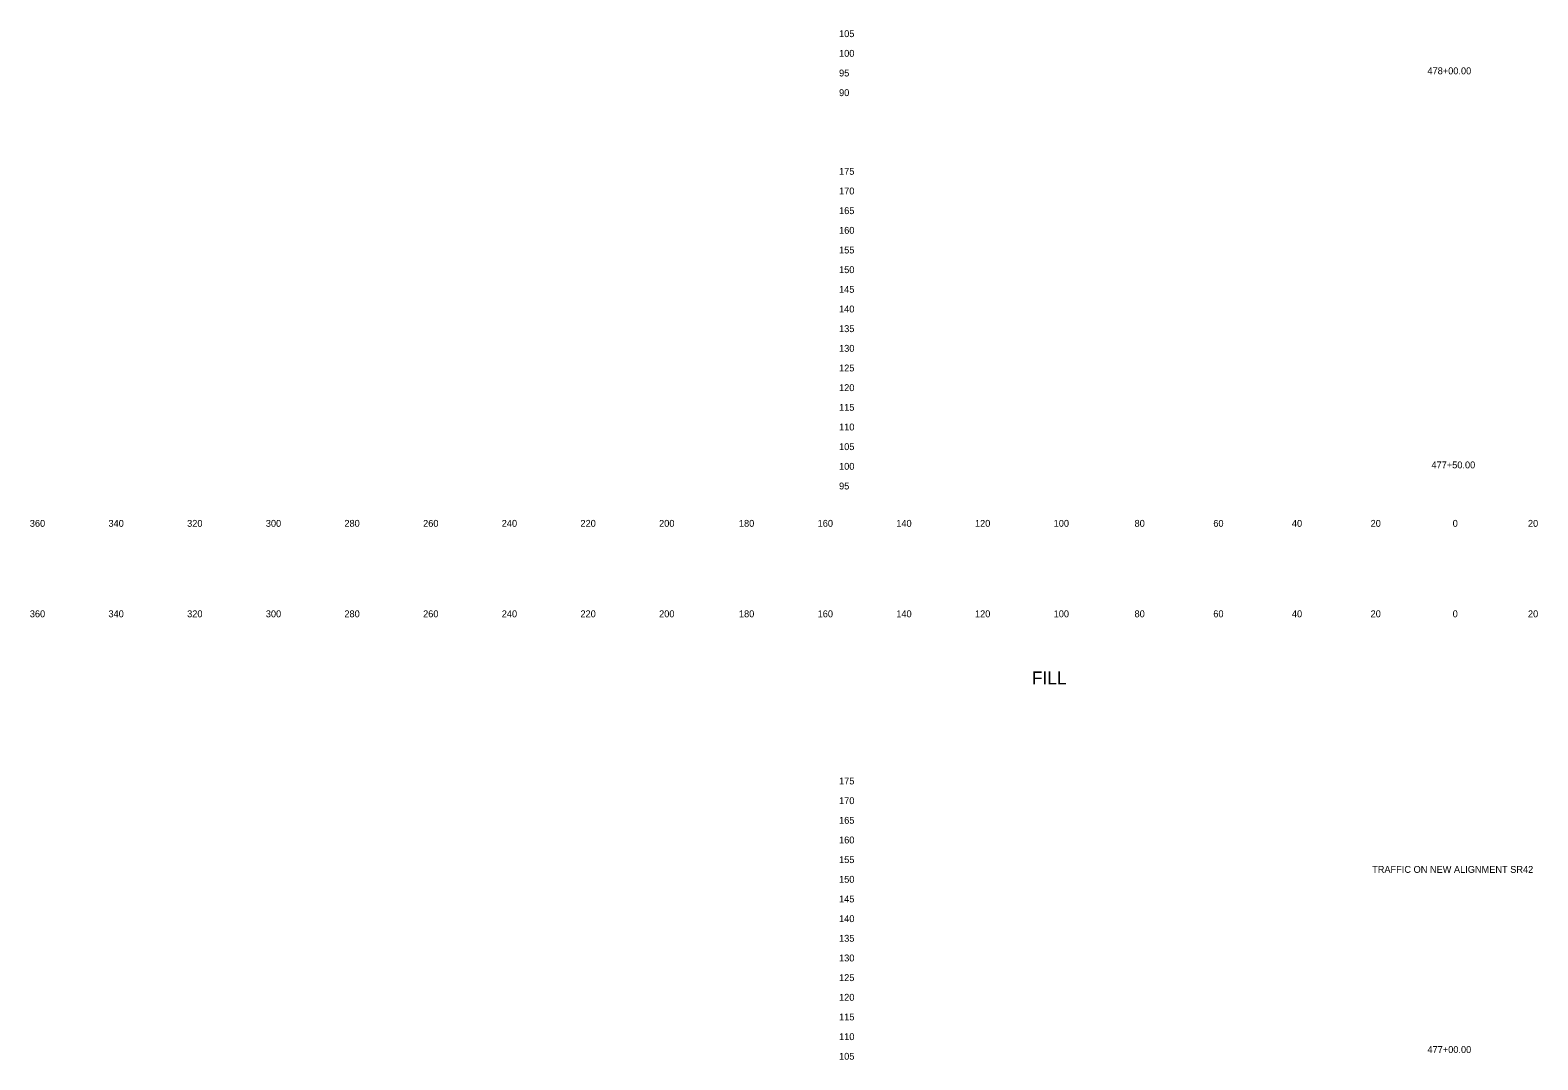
# Model space of a CAD drawing. Extents: x 21281 to 22024, y 6472 to 15208.
# Drawn here: x 21280.5 to 21663.8, y 11399.8 to 11661.6 of the extents above; entities that cross this region are included whole.
import ezdxf

# ---------------------------------------------------------------- set-up
doc = ezdxf.new("R2010")
doc.units = 0
for name, color, linetype in [('XS_SHEET_LABELS_ELEVATION', 7, 'Continuous'), ('XS_SHEET_LABELS_OFFSET', 7, 'Continuous'), ('XS_SHEET_LABELS_STATION', 7, 'Continuous')]:
    doc.layers.add(name, color=color, linetype=linetype)

msp = doc.modelspace()

# ---------------------------------------------------------------- texts
at = {"layer": 'XS_SHEET_LABELS_ELEVATION'}
for s, p in [('  105  ', (21484.84, 11659.84)), ('  100  ', (21484.84, 11654.84)), ('  95  ', (21484.84, 11649.84)), ('  90  ', (21484.84, 11644.84)), ('  175  ', (21484.84, 11624.84)), ('  170  ', (21484.84, 11619.84)), ('  165  ', (21484.84, 11614.84)), ('  160  ', (21484.84, 11609.84)), ('  155  ', (21484.84, 11604.84)), ('  150  ', (21484.84, 11599.84)), ('  145  ', (21484.84, 11594.84)), ('  140  ', (21484.84, 11589.84)), ('  135  ', (21484.84, 11584.84)), ('  130  ', (21484.84, 11579.84)), ('  125  ', (21484.84, 11574.84)), ('  120  ', (21484.84, 11569.84)), ('  115  ', (21484.84, 11564.84)), ('  110  ', (21484.84, 11559.84)), ('  105  ', (21484.84, 11554.84)), ('  100  ', (21484.84, 11549.84)), ('  95  ', (21484.84, 11544.84)), ('  175  ', (21484.84, 11469.84)), ('  170  ', (21484.84, 11464.84)), ('  165  ', (21484.84, 11459.84)), ('  160  ', (21484.84, 11454.84)), ('  155  ', (21484.84, 11449.84)), ('  150  ', (21484.84, 11444.84)), ('  145  ', (21484.84, 11439.84)), ('  140  ', (21484.84, 11434.84)), ('  135  ', (21484.84, 11429.84)), ('  130  ', (21484.84, 11424.84)), ('  125  ', (21484.84, 11419.84)), ('  120  ', (21484.84, 11414.84)), ('  115  ', (21484.84, 11409.84)), ('  110  ', (21484.84, 11404.84)), ('  105  ', (21484.84, 11399.84))]:
    msp.add_text(s, height=1.75, dxfattribs=at).set_placement(p)
at = {"layer": 'XS_SHEET_LABELS_OFFSET'}
for s, height, p in [('  360  ', 1.75, (21279.14, 11535.34)), ('  340  ', 1.75, (21299.13, 11535.34)), ('  320  ', 1.75, (21319.13, 11535.34)), ('  300  ', 1.75, (21339.13, 11535.34)), ('  280  ', 1.75, (21359.1, 11535.34)), ('  260  ', 1.75, (21379.11, 11535.34)), ('  240  ', 1.75, (21399.1, 11535.34)), ('  220  ', 1.75, (21419.1, 11535.34)), ('  200  ', 1.75, (21439.1, 11535.34)), ('  180  ', 1.75, (21459.39, 11535.34)), ('  160  ', 1.75, (21479.4, 11535.34)), ('  140  ', 1.75, (21499.39, 11535.34)), ('  120  ', 1.75, (21519.39, 11535.34)), ('  100  ', 1.75, (21539.39, 11535.34)), ('  80  ', 1.75, (21559.95, 11535.34)), ('  60  ', 1.75, (21579.97, 11535.34)), ('  40  ', 1.75, (21599.95, 11535.34)), ('  20  ', 1.75, (21619.95, 11535.34)), ('  0  ', 1.75, (21640.81, 11535.34)), ('  0  ', 1.75, (21640.81, 11535.34)), ('  20  ', 1.75, (21659.95, 11535.34)), ('  360  ', 1.75, (21279.14, 11512.34)), ('  340  ', 1.75, (21299.13, 11512.34)), ('  320  ', 1.75, (21319.13, 11512.34)), ('  300  ', 1.75, (21339.13, 11512.34)), ('  280  ', 1.75, (21359.1, 11512.34)), ('  260  ', 1.75, (21379.11, 11512.34)), ('  240  ', 1.75, (21399.1, 11512.34)), ('  220  ', 1.75, (21419.1, 11512.34)), ('  200  ', 1.75, (21439.1, 11512.34)), ('  180  ', 1.75, (21459.39, 11512.34)), ('  160  ', 1.75, (21479.4, 11512.34)), ('  140  ', 1.75, (21499.39, 11512.34)), ('  120  ', 1.75, (21519.39, 11512.34)), ('  100  ', 1.75, (21539.39, 11512.34)), ('  80  ', 1.75, (21559.95, 11512.34)), ('  60  ', 1.75, (21579.97, 11512.34)), ('  40  ', 1.75, (21599.95, 11512.34)), ('  20  ', 1.75, (21619.95, 11512.34)), ('  0  ', 1.75, (21640.81, 11512.34)), ('  0  ', 1.75, (21640.81, 11512.34)), ('  20  ', 1.75, (21659.95, 11512.34)), ('FILL', 3.273, (21535.18, 11495.29))]:
    msp.add_text(s, height=height, dxfattribs=at).set_placement(p)
at = {"layer": 'XS_SHEET_LABELS_STATION'}
for s, p in [('  478+00.00  ', (21634.4, 11650.39)), ('  477+50.00  ', (21635.42, 11550.2)), ('TRAFFIC ON NEW ALIGNMENT SR42', (21621.64, 11447.36)), ('  477+00.00  ', (21634.4, 11401.56))]:
    msp.add_text(s, height=1.75, dxfattribs=at).set_placement(p)

doc.saveas('drawing.dxf')
